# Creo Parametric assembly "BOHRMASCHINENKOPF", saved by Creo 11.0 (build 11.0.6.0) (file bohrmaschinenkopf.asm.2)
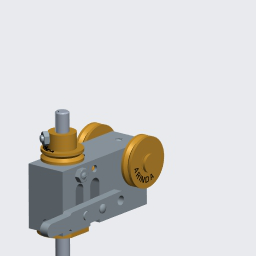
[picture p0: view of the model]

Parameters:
  ERSTELLER = "ARINDA"
  BENENNUNG = "XXX"
  TEILETYP = "K"

Other parameters: MASSE

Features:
  1. coordinate system
  2. datum plane "A_RECHTS_Y-Z"
  3. datum plane "A_OBEN_X-Z"
  4. datum plane "A_VORNE_X-Y"
  5. datum axis
  6. datum axis
  7. datum axis
  8. datum point "APNT0"
  9. component "GETRIEBEGEHÄUSE"
  10. component "UMLENKROLLE-ACHSE"
  11. component "ISO7434_M4X4"
  12. component "UMLENKROLLE"
  13. component "UMLENKROLLE"
  14. component "SPINDELFÜHRUNG"
  15. component "ISO7434_M4X4"
  16. component "ISO2338"
  17. component "UMLENKROLLE-SPINDEL"
  18. component "ISO7435"
  19. component "ISO4032_1", "ISO4032_1M3.PRT"
  20. component "BOHRSPINDEL"
  21. component "ISO7435", "ISO7435_M3.PRT"
  22. component "ISO4032_1", "ISO4032_1M3.PRT"
  23. component "HEBEL"
  24. component "ISO7434_M4X4"

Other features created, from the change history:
  planar section "XSEC0001"
  planar section "B"

Other named items: AA_X, AA_Y, AA_Z, ACS0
